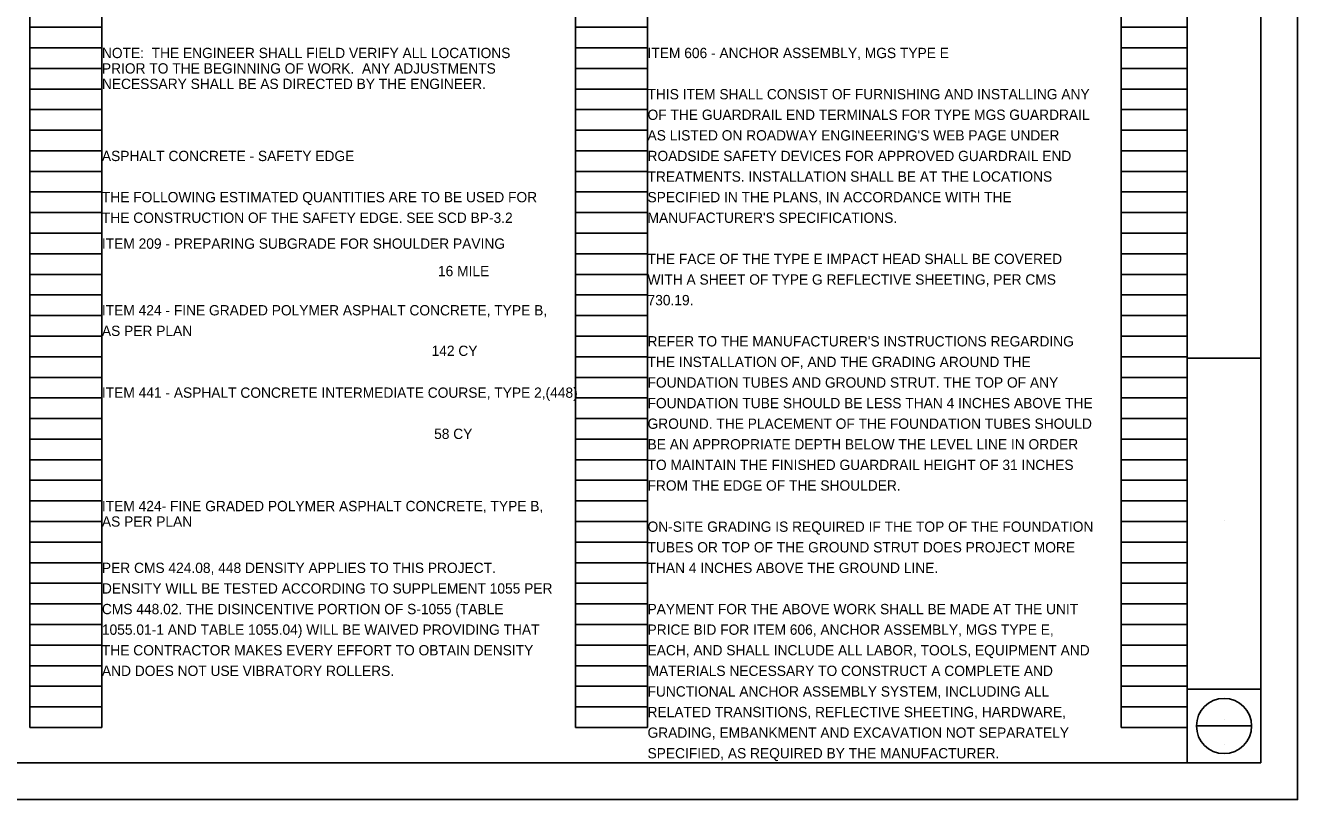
# Model space of a CAD drawing. Extents: x 0 to 34, y 0 to 22.
# Drawn here: x 16.7 to 34, y 0 to 10.52 of the extents above; entities that cross this region are included whole.
import ezdxf

# ---------------------------------------------------------------- set-up
doc = ezdxf.new("R2010")
doc.units = 0
for name, color, linetype in [('Default', 7, 'Continuous'), ('SH_Border', 7, 'Continuous'), ('SH_Cut_Line', 7, 'Continuous'), ('SH_Data', 7, 'Continuous'), ('SH_Text', 7, 'Continuous')]:
    doc.layers.add(name, color=color, linetype=linetype)

msp = doc.modelspace()

# ---------------------------------------------------------------- linework, layer by layer
at = {"layer": 'SH_Border'}
for p, q in [((32.5, 0.5), (32.5, 21.5)), ((32.5, 6), (33.5, 6)), ((32.5, 1.5), (33.5, 1.5))]:
    msp.add_line(p, q, dxfattribs=at)
msp.add_lwpolyline([(2, 21.5), (33.5, 21.5), (33.5, 0.5), (2, 0.5)], close=True, dxfattribs=at)
at = {"layer": 'SH_Cut_Line'}
msp.add_lwpolyline([(0, 0), (34, 0), (34, 22), (0, 22)], close=True, dxfattribs=at)
at = {"layer": 'SH_Data'}
for p, q in [((16.76, 0.98), (16.76, 21.14)), ((17.74, 0.98), (17.74, 21.14)), ((24.18, 0.98), (24.18, 21.14)), ((25.16, 0.98), (25.16, 21.14)), ((31.6, 0.98), (31.6, 21.14)), ((32.5, 0.98), (32.5, 21.14)), ((16.76, 10.5), (17.74, 10.5)), ((24.18, 10.5), (25.16, 10.5)), ((31.6, 10.5), (32.5, 10.5)), ((16.76, 10.22), (17.74, 10.22)), ((24.18, 10.22), (25.16, 10.22)), ((31.6, 10.22), (32.5, 10.22)), ((16.76, 9.94), (17.74, 9.94)), ((24.18, 9.94), (25.16, 9.94)), ((31.6, 9.94), (32.5, 9.94)), ((16.76, 9.66), (17.74, 9.66)), ((24.18, 9.66), (25.16, 9.66)), ((31.6, 9.66), (32.5, 9.66)), ((16.76, 9.38), (17.74, 9.38)), ((24.18, 9.38), (25.16, 9.38)), ((31.6, 9.38), (32.5, 9.38)), ((16.76, 9.1), (17.74, 9.1)), ((24.18, 9.1), (25.16, 9.1)), ((31.6, 9.1), (32.5, 9.1)), ((16.76, 8.82), (17.74, 8.82)), ((24.18, 8.82), (25.16, 8.82)), ((31.6, 8.82), (32.5, 8.82)), ((16.76, 8.54), (17.74, 8.54)), ((24.18, 8.54), (25.16, 8.54)), ((31.6, 8.54), (32.5, 8.54)), ((16.76, 8.26), (17.74, 8.26)), ((24.18, 8.26), (25.16, 8.26)), ((31.6, 8.26), (32.5, 8.26)), ((16.76, 7.98), (17.74, 7.98)), ((24.18, 7.98), (25.16, 7.98)), ((31.6, 7.98), (32.5, 7.98)), ((16.76, 7.7), (17.74, 7.7)), ((24.18, 7.7), (25.16, 7.7)), ((31.6, 7.7), (32.5, 7.7)), ((16.76, 7.42), (17.74, 7.42)), ((24.18, 7.42), (25.16, 7.42)), ((31.6, 7.42), (32.5, 7.42)), ((16.76, 7.14), (17.74, 7.14)), ((24.18, 7.14), (25.16, 7.14)), ((31.6, 7.14), (32.5, 7.14)), ((16.76, 6.86), (17.74, 6.86)), ((24.18, 6.86), (25.16, 6.86)), ((31.6, 6.86), (32.5, 6.86)), ((16.76, 6.58), (17.74, 6.58)), ((24.18, 6.58), (25.16, 6.58)), ((31.6, 6.58), (32.5, 6.58)), ((16.76, 6.3), (17.74, 6.3)), ((24.18, 6.3), (25.16, 6.3)), ((31.6, 6.3), (32.5, 6.3)), ((16.76, 6.02), (17.74, 6.02)), ((24.18, 6.02), (25.16, 6.02)), ((31.6, 6.02), (32.5, 6.02)), ((16.76, 5.74), (17.74, 5.74)), ((24.18, 5.74), (25.16, 5.74)), ((31.6, 5.74), (32.5, 5.74)), ((16.76, 5.46), (17.74, 5.46)), ((24.18, 5.46), (25.16, 5.46)), ((31.6, 5.46), (32.5, 5.46)), ((16.76, 5.18), (17.74, 5.18)), ((24.18, 5.18), (25.16, 5.18)), ((31.6, 5.18), (32.5, 5.18)), ((16.76, 4.9), (17.74, 4.9)), ((24.18, 4.9), (25.16, 4.9)), ((31.6, 4.9), (32.5, 4.9)), ((16.76, 4.62), (17.74, 4.62)), ((24.18, 4.62), (25.16, 4.62)), ((31.6, 4.62), (32.5, 4.62)), ((16.76, 4.34), (17.74, 4.34)), ((24.18, 4.34), (25.16, 4.34)), ((31.6, 4.34), (32.5, 4.34)), ((16.76, 4.06), (17.74, 4.06)), ((24.18, 4.06), (25.16, 4.06)), ((31.6, 4.06), (32.5, 4.06)), ((16.76, 3.78), (17.74, 3.78)), ((24.18, 3.78), (25.16, 3.78)), ((31.6, 3.78), (32.5, 3.78)), ((33, 3.792), (33, 3.792)), ((16.76, 3.5), (17.74, 3.5)), ((24.18, 3.5), (25.16, 3.5)), ((31.6, 3.5), (32.5, 3.5)), ((16.76, 3.22), (17.74, 3.22)), ((24.18, 3.22), (25.16, 3.22)), ((31.6, 3.22), (32.5, 3.22)), ((16.76, 2.94), (17.74, 2.94)), ((24.18, 2.94), (25.16, 2.94)), ((31.6, 2.94), (32.5, 2.94)), ((16.76, 2.66), (17.74, 2.66)), ((24.18, 2.66), (25.16, 2.66)), ((31.6, 2.66), (32.5, 2.66)), ((16.76, 2.38), (17.74, 2.38)), ((24.18, 2.38), (25.16, 2.38)), ((31.6, 2.38), (32.5, 2.38)), ((16.76, 2.1), (17.74, 2.1)), ((24.18, 2.1), (25.16, 2.1)), ((31.6, 2.1), (32.5, 2.1)), ((16.76, 1.82), (17.74, 1.82)), ((24.18, 1.82), (25.16, 1.82)), ((31.6, 1.82), (32.5, 1.82)), ((16.76, 1.54), (17.74, 1.54)), ((24.18, 1.54), (25.16, 1.54)), ((31.6, 1.54), (32.5, 1.54)), ((16.76, 1.26), (17.74, 1.26)), ((24.18, 1.26), (25.16, 1.26)), ((31.6, 1.26), (32.5, 1.26)), ((33, 1.085), (33, 1.085)), ((16.76, 0.98), (17.74, 0.98)), ((24.18, 0.98), (25.16, 0.98)), ((31.6, 0.98), (32.5, 0.98)), ((32.625, 1), (33.375, 1)), ((33, 0.745), (33, 0.745))]:
    msp.add_line(p, q, dxfattribs=at)
msp.add_circle((33, 1), 0.375, dxfattribs=at)

# ---------------------------------------------------------------- texts
at = {"layer": 'Default'}
for s, p in [('NOTE:  THE ENGINEER SHALL FIELD VERIFY ALL LOCATIONS', (17.74, 10.08)), ('PRIOR TO THE BEGINNING OF WORK.  ANY ADJUSTMENTS', (17.74, 9.87)), ('NECESSARY SHALL BE AS DIRECTED BY THE ENGINEER.', (17.74, 9.66))]:
    msp.add_text(s, height=0.14, dxfattribs=at).set_placement(p)
at = {"layer": 'SH_Text'}
for s, p in [('ITEM 606 - ANCHOR ASSEMBLY, MGS TYPE E', (25.16, 10.08)), ('THIS ITEM SHALL CONSIST OF FURNISHING AND INSTALLING ANY', (25.16, 9.52)), ('OF THE GUARDRAIL END TERMINALS FOR TYPE MGS GUARDRAIL', (25.16, 9.24)), ("AS LISTED ON ROADWAY ENGINEERING'S WEB PAGE UNDER", (25.16, 8.96)), ('ASPHALT CONCRETE - SAFETY EDGE', (17.74, 8.68)), ('ROADSIDE SAFETY DEVICES FOR APPROVED GUARDRAIL END', (25.16, 8.68)), ('TREATMENTS. INSTALLATION SHALL BE AT THE LOCATIONS', (25.16, 8.4)), ('THE FOLLOWING ESTIMATED QUANTITIES ARE TO BE USED FOR', (17.74, 8.12)), ('SPECIFIED IN THE PLANS, IN ACCORDANCE WITH THE', (25.16, 8.12)), ('THE CONSTRUCTION OF THE SAFETY EDGE. SEE SCD BP-3.2', (17.74, 7.84)), ("MANUFACTURER'S SPECIFICATIONS.", (25.16, 7.84)), ('ITEM 209 - PREPARING SUBGRADE FOR SHOULDER PAVING', (17.74, 7.488)), ('THE FACE OF THE TYPE E IMPACT HEAD SHALL BE COVERED', (25.16, 7.28)), ('16 MILE', (22.31, 7.115)), ('WITH A SHEET OF TYPE G REFLECTIVE SHEETING, PER CMS', (25.16, 7)), ('730.19.', (25.16, 6.72)), ('ITEM 424 - FINE GRADED POLYMER ASPHALT CONCRETE, TYPE B,', (17.74, 6.582)), ('AS PER PLAN', (17.74, 6.302)), ("REFER TO THE MANUFACTURER'S INSTRUCTIONS REGARDING", (25.16, 6.16)), ('142 CY', (22.223, 6.031)), ('THE INSTALLATION OF, AND THE GRADING AROUND THE', (25.16, 5.88)), ('FOUNDATION TUBES AND GROUND STRUT. THE TOP OF ANY', (25.16, 5.6)), ('ITEM 441 - ASPHALT CONCRETE INTERMEDIATE COURSE, TYPE 2,(448)', (17.74, 5.462)), ('FOUNDATION TUBE SHOULD BE LESS THAN 4 INCHES ABOVE THE', (25.16, 5.32)), ('58 CY', (22.258, 4.902)), ('GROUND. THE PLACEMENT OF THE FOUNDATION TUBES SHOULD', (25.16, 5.04)), ('BE AN APPROPRIATE DEPTH BELOW THE LEVEL LINE IN ORDER', (25.16, 4.76)), ('TO MAINTAIN THE FINISHED GUARDRAIL HEIGHT OF 31 INCHES', (25.16, 4.48)), ('FROM THE EDGE OF THE SHOULDER.', (25.16, 4.2)), ('ITEM 424- FINE GRADED POLYMER ASPHALT CONCRETE, TYPE B, ', (17.74, 3.92)), ('AS PER PLAN', (17.74, 3.71)), ('ON-SITE GRADING IS REQUIRED IF THE TOP OF THE FOUNDATION', (25.16, 3.64)), ('TUBES OR TOP OF THE GROUND STRUT DOES PROJECT MORE', (25.16, 3.36)), ('PER CMS 424.08, 448 DENSITY APPLIES TO THIS PROJECT.', (17.74, 3.08)), ('THAN 4 INCHES ABOVE THE GROUND LINE.', (25.16, 3.08)), ('DENSITY WILL BE TESTED ACCORDING TO SUPPLEMENT 1055 PER', (17.74, 2.8)), ('CMS 448.02. THE DISINCENTIVE PORTION OF S-1055 (TABLE', (17.74, 2.52)), ('PAYMENT FOR THE ABOVE WORK SHALL BE MADE AT THE UNIT', (25.16, 2.52)), ('1055.01-1 AND TABLE 1055.04) WILL BE WAIVED PROVIDING THAT', (17.74, 2.24)), ('PRICE BID FOR ITEM 606, ANCHOR ASSEMBLY, MGS TYPE E,', (25.16, 2.24)), ('THE CONTRACTOR MAKES EVERY EFFORT TO OBTAIN DENSITY', (17.74, 1.96)), ('EACH, AND SHALL INCLUDE ALL LABOR, TOOLS, EQUIPMENT AND', (25.16, 1.96)), ('AND DOES NOT USE VIBRATORY ROLLERS.', (17.74, 1.68)), ('MATERIALS NECESSARY TO CONSTRUCT A COMPLETE AND', (25.16, 1.68)), ('FUNCTIONAL ANCHOR ASSEMBLY SYSTEM, INCLUDING ALL', (25.16, 1.4)), ('RELATED TRANSITIONS, REFLECTIVE SHEETING, HARDWARE,', (25.16, 1.12)), ('GRADING, EMBANKMENT AND EXCAVATION NOT SEPARATELY', (25.16, 0.84)), ('SPECIFIED, AS REQUIRED BY THE MANUFACTURER.', (25.16, 0.56))]:
    msp.add_text(s, height=0.14, dxfattribs=at).set_placement(p)

doc.saveas('drawing.dxf')
